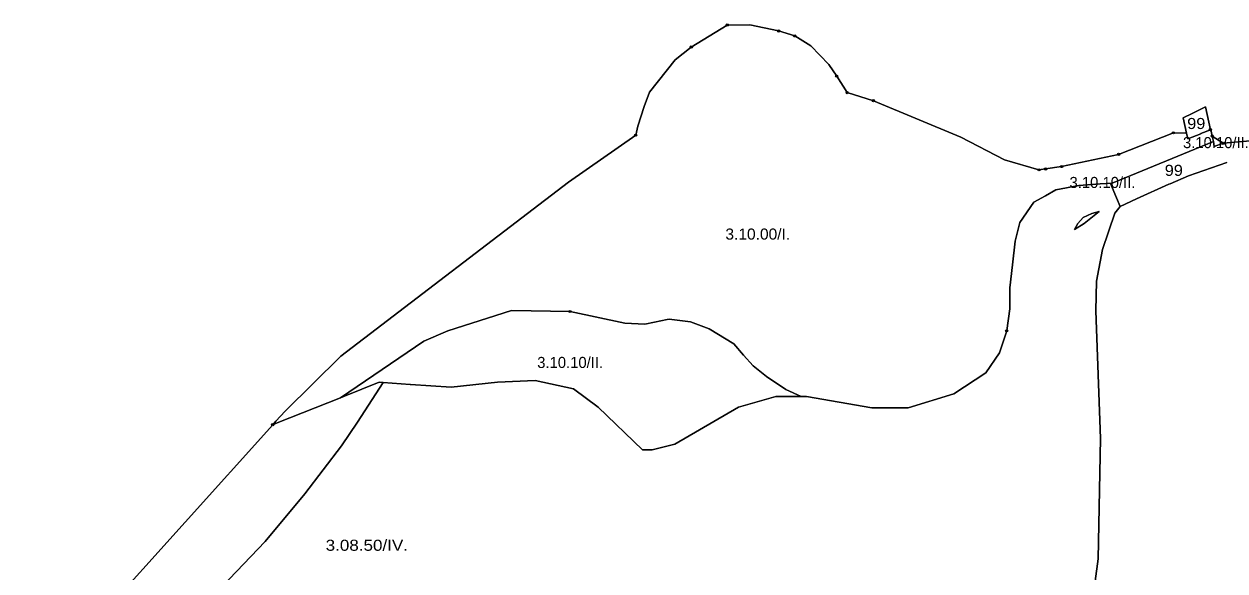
# Model space of a CAD drawing. Extents: x -650455 to -642254, y -1075222 to -1066610.
# Drawn here: x -645923 to -644838, y -1069403 to -1068909 of the extents above; entities that cross this region are included whole.
import ezdxf
from ezdxf.enums import TextEntityAlignment as Align

# ---------------------------------------------------------------- set-up
doc = ezdxf.new("R2010")
doc.units = 0
doc.header["$LTSCALE"] = 4
doc.header["$PDMODE"] = 32
doc.header["$PDSIZE"] = 2
for name, color, linetype, lineweight in [('1', 7, 'Continuous', 25), ('11', 7, 'Continuous', 13), ('12', 7, 'Continuous', 13), ('14', 7, 'Continuous', 13), ('15', 7, 'Continuous', 13), ('16', 7, 'Continuous', 13)]:
    doc.layers.add(name, color=color, linetype=linetype, lineweight=lineweight)
doc.layers.add('2', color=7, linetype='Continuous')

msp = doc.modelspace()

# ---------------------------------------------------------------- linework, layer by layer
at = {"layer": '1'}
for points in [[(-644794, -1069012.5), (-644839.5, -1069016.5), (-644849.51, -1069009.955), (-644850.813, -1069004.126), (-644851.147, -1069004.26), (-644851.16, -1069004.211), (-644855.56, -1068983.38), (-644867.701, -1068989.497), (-644875.563, -1068993.501), (-644872.563, -1069007.374), (-644884.5, -1069007), (-644934, -1069026.501), (-644985.5, -1069037.501), (-645000, -1069039.622), (-645006, -1069040.5), (-645037, -1069031.5), (-645076.5, -1069011), (-645155.5, -1068978.001), (-645179.25, -1068970.626), (-645188.625, -1068955.75), (-645195.875, -1068945.251), (-645212.063, -1068928.251), (-645226.625, -1068919.376), (-645241.125, -1068914.876), (-645267.188, -1068909.375), (-645287.562, -1068909.625), (-645320.062, -1068929.501), (-645334.5, -1068940.875), (-645357.687, -1068970.375), (-645362.563, -1068983.25), (-645368.25, -1069001.125), (-645370.25, -1069009.125), (-645431, -1069051.5), (-645636.5, -1069209.001), (-645687, -1069258.5), (-645695.188, -1069267.626), (-645695.195, -1069267.614), (-645698.133, -1069270.881), (-645856.5, -1069447.001)], [(-645341.813, -1069175.875), (-645353.25, -1069178.25), (-645362, -1069180.001), (-645380, -1069179), (-645429.5, -1069168.501), (-645482.5, -1069167.501), (-645540, -1069186), (-645561.5, -1069195.501), (-645637, -1069246.5), (-645694.125, -1069269.251), (-645694.109, -1069269.277), (-645698.133, -1069270.881), (-645695.195, -1069267.614), (-645695.188, -1069267.626), (-645687, -1069258.5), (-645636.5, -1069209.001), (-645431, -1069051.5), (-645370.25, -1069009.125), (-645368.25, -1069001.125), (-645362.563, -1068983.25), (-645357.687, -1068970.375), (-645334.5, -1068940.875), (-645320.062, -1068929.501), (-645287.562, -1068909.625), (-645267.188, -1068909.375), (-645241.125, -1068914.876), (-645226.625, -1068919.376), (-645212.063, -1068928.251), (-645195.875, -1068945.251), (-645188.625, -1068955.75), (-645179.25, -1068970.626), (-645155.5, -1068978.001), (-645076.5, -1069011), (-645037, -1069031.5), (-645006, -1069040.5), (-645000, -1069039.622), (-644985.5, -1069037.501), (-644934, -1069026.501), (-644884.5, -1069007), (-644872.563, -1069007.374)], [(-644872.563, -1069007.374), (-644871.437, -1069012.5), (-644859.861, -1069007.77), (-644859.813, -1069007.75), (-644851.147, -1069004.26), (-644850.813, -1069004.126), (-644849.51, -1069009.955), (-644849.5, -1069010.001), (-644848.375, -1069014.875), (-644939.937, -1069052.376), (-644950.812, -1069053), (-644969.937, -1069054.625), (-644990.688, -1069058.625), (-645000, -1069063.822), (-645010.625, -1069069.751), (-645023.375, -1069088.126), (-645027.375, -1069104.876), (-645029.75, -1069126.376), (-645032.188, -1069147.125), (-645032.188, -1069166.25), (-645035.036, -1069185.816), (-645035.062, -1069186), (-645041.5, -1069206), (-645054, -1069224.001), (-645083, -1069243), (-645124, -1069255.5), (-645157, -1069255.5), (-645216, -1069245.501), (-645220.813, -1069245.501), (-645234.625, -1069239.126), (-645252.125, -1069227.25), (-645264.125, -1069217.626), (-645272.875, -1069208.125), (-645281.687, -1069197.75), (-645304, -1069184.125), (-645320.75, -1069177.75), (-645339.858, -1069175.378), (-645339.875, -1069175.375), (-645341.733, -1069175.855), (-645341.813, -1069175.875)], [(-644836.38, -1069033.691), (-644871, -1069046.001), (-644887.558, -1069053.097), (-644888.516, -1069053.508), (-644917.772, -1069066.77), (-644932.672, -1069073.465), (-644932.75, -1069073.5), (-644935.995, -1069065.887), (-644936, -1069065.875), (-644941.25, -1069052.876), (-644939.937, -1069052.376), (-644848.375, -1069014.875), (-644847.625, -1069019.376), (-644847.621, -1069019.397), (-644839.5, -1069016.5), (-644794, -1069012.5)], [(-644958, -1069432.5), (-644952.5, -1069392), (-644950.5, -1069283.5), (-644954.5, -1069168.001), (-644954, -1069141), (-644948.5, -1069112.5), (-644937.5, -1069079.501), (-644932.672, -1069073.465), (-644917.772, -1069066.77), (-644888.516, -1069053.508), (-644887.558, -1069053.097), (-644871, -1069046.001), (-644836.38, -1069033.691)], [(-645461, -1069231), (-645426.5, -1069238.5), (-645404, -1069255), (-645364, -1069293.501), (-645355.5, -1069293.501), (-645335, -1069288.501), (-645277.5, -1069255), (-645243.5, -1069245.501), (-645220.813, -1069245.501), (-645216, -1069245.501), (-645157, -1069255.5), (-645124, -1069255.5), (-645083, -1069243), (-645054, -1069224.001), (-645041.5, -1069206), (-645035.062, -1069186), (-645035.036, -1069185.816), (-645032.188, -1069166.25), (-645032.188, -1069147.125), (-645029.75, -1069126.376), (-645027.375, -1069104.876), (-645023.375, -1069088.126), (-645010.625, -1069069.751), (-645000, -1069063.822), (-644990.688, -1069058.625), (-644969.937, -1069054.625), (-644950.812, -1069053), (-644939.937, -1069052.376), (-644941.25, -1069052.876), (-644936, -1069065.875), (-644935.995, -1069065.887), (-644932.75, -1069073.5), (-644932.672, -1069073.465)], [(-644932.672, -1069073.465), (-644937.5, -1069079.501), (-644948.5, -1069112.5), (-644954, -1069141), (-644954.5, -1069168.001), (-644950.5, -1069283.5), (-644952.5, -1069392), (-644958, -1069432.5)], [(-645763.379, -1069437.622), (-645704.82, -1069376.516), (-645669.175, -1069333.233), (-645636.076, -1069289.95), (-645621.437, -1069268.627), (-645598.374, -1069232.751), (-645573.808, -1069234.452), (-645573.688, -1069234.5), (-645537, -1069237.001), (-645495, -1069232.501), (-645461, -1069231)], [(-645960, -1069928), (-645957.5, -1069916.501), (-645945.5, -1069826), (-645941.5, -1069786), (-645925, -1069683.5), (-645928.5, -1069687.5), (-645921.5, -1069660.5), (-645908.5, -1069548.001), (-645886.5, -1069492.001), (-645856.5, -1069447.001), (-645698.133, -1069270.881), (-645694.109, -1069269.277), (-645694.125, -1069269.251), (-645637, -1069246.5), (-645633.75, -1069245.251), (-645633.394, -1069245.058), (-645602, -1069232.501), (-645598.374, -1069232.751)], [(-645598.374, -1069232.751), (-645621.437, -1069268.627), (-645636.076, -1069289.95), (-645669.175, -1069333.233), (-645704.82, -1069376.516), (-645763.379, -1069437.622)]]:
    msp.add_lwpolyline(points, dxfattribs=at)
for points in [[(-644851.147, -1069004.26), (-644859.813, -1069007.75), (-644859.861, -1069007.77), (-644871.437, -1069012.5), (-644872.563, -1069007.374), (-644875.563, -1068993.501), (-644867.701, -1068989.497), (-644855.56, -1068983.38), (-644851.16, -1069004.211)], [(-644839.5, -1069016.5), (-644847.621, -1069019.397), (-644847.625, -1069019.376), (-644848.375, -1069014.875), (-644849.5, -1069010.001), (-644849.51, -1069009.955)], [(-644965, -1069089), (-644951.514, -1069078.254), (-644958.188, -1069079.876), (-644965.937, -1069083.625), (-644971, -1069088.876), (-644973.937, -1069094.375), (-644973.944, -1069094.389)], [(-644965, -1069089), (-644973.944, -1069094.389), (-644973.937, -1069094.375), (-644971, -1069088.876), (-644965.937, -1069083.625), (-644958.188, -1069079.876), (-644951.514, -1069078.254)], [(-645220.813, -1069245.501), (-645243.5, -1069245.501), (-645277.5, -1069255), (-645335, -1069288.501), (-645355.5, -1069293.501), (-645364, -1069293.501), (-645404, -1069255), (-645426.5, -1069238.5), (-645461, -1069231), (-645495, -1069232.501), (-645537, -1069237.001), (-645573.688, -1069234.5), (-645573.808, -1069234.452), (-645598.374, -1069232.751), (-645602, -1069232.501), (-645633.394, -1069245.058), (-645633.75, -1069245.251), (-645637, -1069246.5), (-645561.5, -1069195.501), (-645540, -1069186), (-645482.5, -1069167.501), (-645429.5, -1069168.501), (-645380, -1069179), (-645362, -1069180.001), (-645353.25, -1069178.25), (-645341.813, -1069175.875), (-645341.733, -1069175.855), (-645339.875, -1069175.375), (-645339.858, -1069175.378), (-645320.75, -1069177.75), (-645304, -1069184.125), (-645281.687, -1069197.75), (-645272.875, -1069208.125), (-645264.125, -1069217.626), (-645252.125, -1069227.25), (-645234.625, -1069239.126)]]:
    msp.add_lwpolyline(points, close=True, dxfattribs=at)
at = {"layer": '11'}
for p, q in [((-645179.25, -1068970.626), (-645188.625, -1068955.75)), ((-645000, -1069039.622), (-644985.5, -1069037.501))]:
    msp.add_line(p, q, dxfattribs=at)
for points in [[(-645370.25, -1069009.125), (-645368.25, -1069001.125), (-645362.563, -1068983.25), (-645357.687, -1068970.375), (-645334.5, -1068940.875), (-645320.062, -1068929.501), (-645287.562, -1068909.625)], [(-645241.125, -1068914.876), (-645267.188, -1068909.375), (-645287.562, -1068909.625), (-645320.062, -1068929.501)], [(-645287.562, -1068909.625), (-645267.188, -1068909.375), (-645241.125, -1068914.876), (-645226.625, -1068919.376)], [(-645188.625, -1068955.75), (-645195.875, -1068945.251), (-645212.063, -1068928.251), (-645226.625, -1068919.376), (-645241.125, -1068914.876)], [(-645226.625, -1068919.376), (-645212.063, -1068928.251), (-645195.875, -1068945.251), (-645188.625, -1068955.75), (-645179.25, -1068970.626), (-645155.5, -1068978.001)], [(-645320.062, -1068929.501), (-645334.5, -1068940.875), (-645357.687, -1068970.375), (-645362.563, -1068983.25), (-645368.25, -1069001.125), (-645370.25, -1069009.125), (-645431, -1069051.5), (-645636.5, -1069209.001), (-645687, -1069258.5), (-645695.188, -1069267.626), (-645695.195, -1069267.614), (-645698.133, -1069270.881), (-645694.109, -1069269.277), (-645694.125, -1069269.251), (-645637, -1069246.5), (-645561.5, -1069195.501), (-645540, -1069186), (-645482.5, -1069167.501), (-645429.5, -1069168.501)], [(-645006, -1069040.5), (-645037, -1069031.5), (-645076.5, -1069011), (-645155.5, -1068978.001), (-645179.25, -1068970.626)], [(-645155.5, -1068978.001), (-645076.5, -1069011), (-645037, -1069031.5), (-645006, -1069040.5), (-645000, -1069039.622)], [(-644884.5, -1069007), (-644872.563, -1069007.374), (-644875.563, -1068993.501), (-644867.701, -1068989.497), (-644855.56, -1068983.38), (-644851.16, -1069004.211), (-644851.147, -1069004.26), (-644850.813, -1069004.126), (-644849.51, -1069009.955), (-644839.5, -1069016.5), (-644794, -1069012.5), (-644730, -1069011.5), (-644677, -1069006.501), (-644667.5, -1068997.501)], [(-644849.51, -1069009.955), (-644850.813, -1069004.126), (-644851.147, -1069004.26), (-644859.813, -1069007.75), (-644859.861, -1069007.77), (-644871.437, -1069012.5), (-644872.563, -1069007.374), (-644884.5, -1069007), (-644934, -1069026.501)], [(-645941.5, -1069786), (-645925, -1069683.5), (-645928.5, -1069687.5), (-645921.5, -1069660.5), (-645908.5, -1069548.001), (-645886.5, -1069492.001), (-645856.5, -1069447.001), (-645698.133, -1069270.881), (-645695.195, -1069267.614), (-645695.188, -1069267.626), (-645687, -1069258.5), (-645636.5, -1069209.001), (-645431, -1069051.5), (-645370.25, -1069009.125)], [(-645429.5, -1069168.501), (-645380, -1069179), (-645362, -1069180.001), (-645353.25, -1069178.25), (-645341.813, -1069175.875), (-645341.733, -1069175.855), (-645339.875, -1069175.375), (-645339.858, -1069175.378), (-645320.75, -1069177.75), (-645304, -1069184.125), (-645281.687, -1069197.75), (-645272.875, -1069208.125), (-645264.125, -1069217.626), (-645252.125, -1069227.25), (-645234.625, -1069239.126), (-645220.813, -1069245.501), (-645216, -1069245.501), (-645157, -1069255.5), (-645124, -1069255.5), (-645083, -1069243), (-645054, -1069224.001), (-645041.5, -1069206), (-645035.062, -1069186), (-645035.036, -1069185.816), (-645032.188, -1069166.25), (-645032.188, -1069147.125), (-645029.75, -1069126.376), (-645027.375, -1069104.876), (-645023.375, -1069088.126), (-645010.625, -1069069.751), (-645000, -1069063.822), (-644990.688, -1069058.625), (-644969.937, -1069054.625), (-644950.812, -1069053), (-644939.937, -1069052.376), (-644848.375, -1069014.875), (-644849.5, -1069010.001), (-644849.51, -1069009.955)], [(-644985.5, -1069037.501), (-644934, -1069026.501), (-644884.5, -1069007)], [(-644836.38, -1069033.691), (-644871, -1069046.001), (-644887.558, -1069053.097), (-644888.516, -1069053.508), (-644917.772, -1069066.77), (-644932.672, -1069073.465), (-644937.5, -1069079.501), (-644948.5, -1069112.5), (-644954, -1069141), (-644954.5, -1069168.001), (-644950.5, -1069283.5), (-644952.5, -1069392), (-644958, -1069432.5), (-644973, -1069470.5), (-645000, -1069517.419), (-645003.5, -1069523.501), (-645037, -1069572.001), (-645098.5, -1069631), (-645124.5, -1069647.5), (-645146, -1069654.001), (-645167.5, -1069654.001)], [(-644934, -1069026.501), (-644985.5, -1069037.501), (-645000, -1069039.622), (-645006, -1069040.5)]]:
    msp.add_lwpolyline(points, dxfattribs=at)
for p in [(-645287.562, -1068909.625), (-645241.125, -1068914.876), (-645226.625, -1068919.376), (-645320.062, -1068929.501), (-645188.625, -1068955.75), (-645179.25, -1068970.626), (-645155.5, -1068978.001), (-645370.25, -1069009.125), (-644884.5, -1069007), (-644849.51, -1069009.955), (-644934, -1069026.501), (-644985.5, -1069037.501), (-645006, -1069040.5), (-645000, -1069039.622)]:
    msp.add_point(p, dxfattribs=at)
at = {"layer": '12'}
for points in [[(-644839.5, -1069016.5), (-644849.51, -1069009.955), (-644849.5, -1069010.001), (-644848.375, -1069014.875), (-644847.625, -1069019.376)], [(-644847.625, -1069019.376), (-644847.621, -1069019.397), (-644839.5, -1069016.5)], [(-645429.5, -1069168.501), (-645482.5, -1069167.501), (-645540, -1069186), (-645561.5, -1069195.501), (-645637, -1069246.5), (-645633.75, -1069245.251), (-645633.394, -1069245.058), (-645602, -1069232.501), (-645598.374, -1069232.751), (-645573.808, -1069234.452), (-645573.688, -1069234.5), (-645537, -1069237.001), (-645495, -1069232.501), (-645461, -1069231), (-645426.5, -1069238.5), (-645404, -1069255), (-645364, -1069293.501)], [(-645364, -1069293.501), (-645355.5, -1069293.501), (-645335, -1069288.501), (-645277.5, -1069255), (-645243.5, -1069245.501), (-645220.813, -1069245.501), (-645234.625, -1069239.126), (-645252.125, -1069227.25), (-645264.125, -1069217.626), (-645272.875, -1069208.125), (-645281.687, -1069197.75), (-645304, -1069184.125), (-645320.75, -1069177.75), (-645339.858, -1069175.378), (-645339.875, -1069175.375), (-645341.733, -1069175.855), (-645341.813, -1069175.875), (-645353.25, -1069178.25), (-645362, -1069180.001), (-645380, -1069179), (-645429.5, -1069168.501)]]:
    msp.add_lwpolyline(points, dxfattribs=at)
for p in [(-644839.5, -1069016.5), (-645429.5, -1069168.501)]:
    msp.add_point(p, dxfattribs=at)
at = {"layer": '14'}
for points in [[(-644958, -1069432.5), (-644952.5, -1069392), (-644950.5, -1069283.5), (-644954.5, -1069168.001), (-644954, -1069141), (-644948.5, -1069112.5), (-644937.5, -1069079.501), (-644932.672, -1069073.465), (-644932.75, -1069073.5), (-644935.995, -1069065.887), (-644936, -1069065.875), (-644941.25, -1069052.876), (-644939.937, -1069052.376), (-644950.812, -1069053), (-644969.937, -1069054.625), (-644990.688, -1069058.625), (-645000, -1069063.822), (-645010.625, -1069069.751), (-645023.375, -1069088.126), (-645027.375, -1069104.876), (-645029.75, -1069126.376), (-645032.188, -1069147.125)], [(-645032.188, -1069147.125), (-645032.188, -1069166.25), (-645035.036, -1069185.816), (-645035.062, -1069186)], [(-645035.062, -1069186), (-645041.5, -1069206), (-645054, -1069224.001), (-645083, -1069243), (-645124, -1069255.5), (-645157, -1069255.5), (-645216, -1069245.501), (-645220.813, -1069245.501), (-645243.5, -1069245.501), (-645277.5, -1069255), (-645335, -1069288.501), (-645355.5, -1069293.501), (-645364, -1069293.501), (-645404, -1069255), (-645426.5, -1069238.5), (-645461, -1069231), (-645495, -1069232.501), (-645537, -1069237.001), (-645573.688, -1069234.5), (-645573.808, -1069234.452), (-645598.374, -1069232.751), (-645621.437, -1069268.627), (-645636.076, -1069289.95), (-645669.175, -1069333.233), (-645704.82, -1069376.516), (-645763.379, -1069437.622)]]:
    msp.add_lwpolyline(points, dxfattribs=at)
msp.add_point((-645035.062, -1069186), dxfattribs=at)
at = {"layer": '15'}
for points in [[(-645854.14, -1069705.005), (-645856.947, -1069657.538), (-645856.947, -1069611.709), (-645854.401, -1069578.61), (-645844.217, -1069553.15), (-645811.118, -1069499.682), (-645798.388, -1069481.86), (-645763.379, -1069437.622), (-645704.82, -1069376.516), (-645669.175, -1069333.233), (-645636.076, -1069289.95), (-645621.437, -1069268.627), (-645598.374, -1069232.751), (-645602, -1069232.501), (-645633.394, -1069245.058), (-645633.75, -1069245.251), (-645637, -1069246.5), (-645694.125, -1069269.251), (-645694.109, -1069269.277), (-645698.133, -1069270.881)], [(-645698.133, -1069270.881), (-645856.5, -1069447.001), (-645886.5, -1069492.001), (-645908.5, -1069548.001), (-645921.5, -1069660.5)]]:
    msp.add_lwpolyline(points, dxfattribs=at)
msp.add_point((-645698.133, -1069270.881), dxfattribs=at)
at = {"layer": '16'}
for points in [[(-644851.16, -1069004.211), (-644855.56, -1068983.38), (-644867.701, -1068989.497), (-644875.563, -1068993.501), (-644872.563, -1069007.374), (-644871.437, -1069012.5)], [(-644871.437, -1069012.5), (-644859.861, -1069007.77), (-644859.813, -1069007.75), (-644851.147, -1069004.26), (-644851.16, -1069004.211)], [(-644794, -1069012.5), (-644839.5, -1069016.5), (-644847.621, -1069019.397), (-644847.625, -1069019.376), (-644848.375, -1069014.875), (-644939.937, -1069052.376), (-644941.25, -1069052.876), (-644936, -1069065.875), (-644935.995, -1069065.887), (-644932.75, -1069073.5), (-644932.672, -1069073.465), (-644917.772, -1069066.77), (-644888.516, -1069053.508), (-644887.558, -1069053.097), (-644871, -1069046.001), (-644836.38, -1069033.691)]]:
    msp.add_lwpolyline(points, dxfattribs=at)
msp.add_point((-644851.16, -1069004.211), dxfattribs=at)

# ---------------------------------------------------------------- texts
at = {"layer": '2'}
for s, width, p in [('99', 1.1, (-644863.885, -1069003.583)), ('99', 1.1, (-644884.152, -1069045.92)), ('3.10.00/I.', 1.05, (-645259.949, -1069103.522)), ('3.08.50/IV.', 1.15, (-645613.096, -1069384.866))]:
    msp.add_text(s, height=10, dxfattribs=dict(at, width=width)).set_placement(p, align=Align.CENTER)
for p in [(-644846.118, -1069020.872), (-644948.622, -1069056.876), (-645429.422, -1069219.594)]:
    msp.add_text('3.10.10/II.', height=10, dxfattribs=at).set_placement(p, align=Align.CENTER)

doc.saveas('drawing.dxf')
